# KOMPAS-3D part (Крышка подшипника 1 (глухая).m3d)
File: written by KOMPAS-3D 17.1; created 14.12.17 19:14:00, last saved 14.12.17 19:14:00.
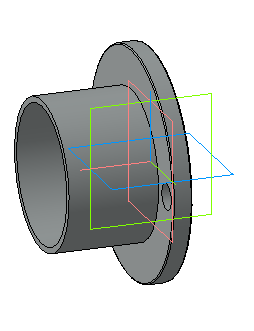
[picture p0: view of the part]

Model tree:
1. Операция без истории:1  (labels: Крышка подшипника 1 (глухая))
